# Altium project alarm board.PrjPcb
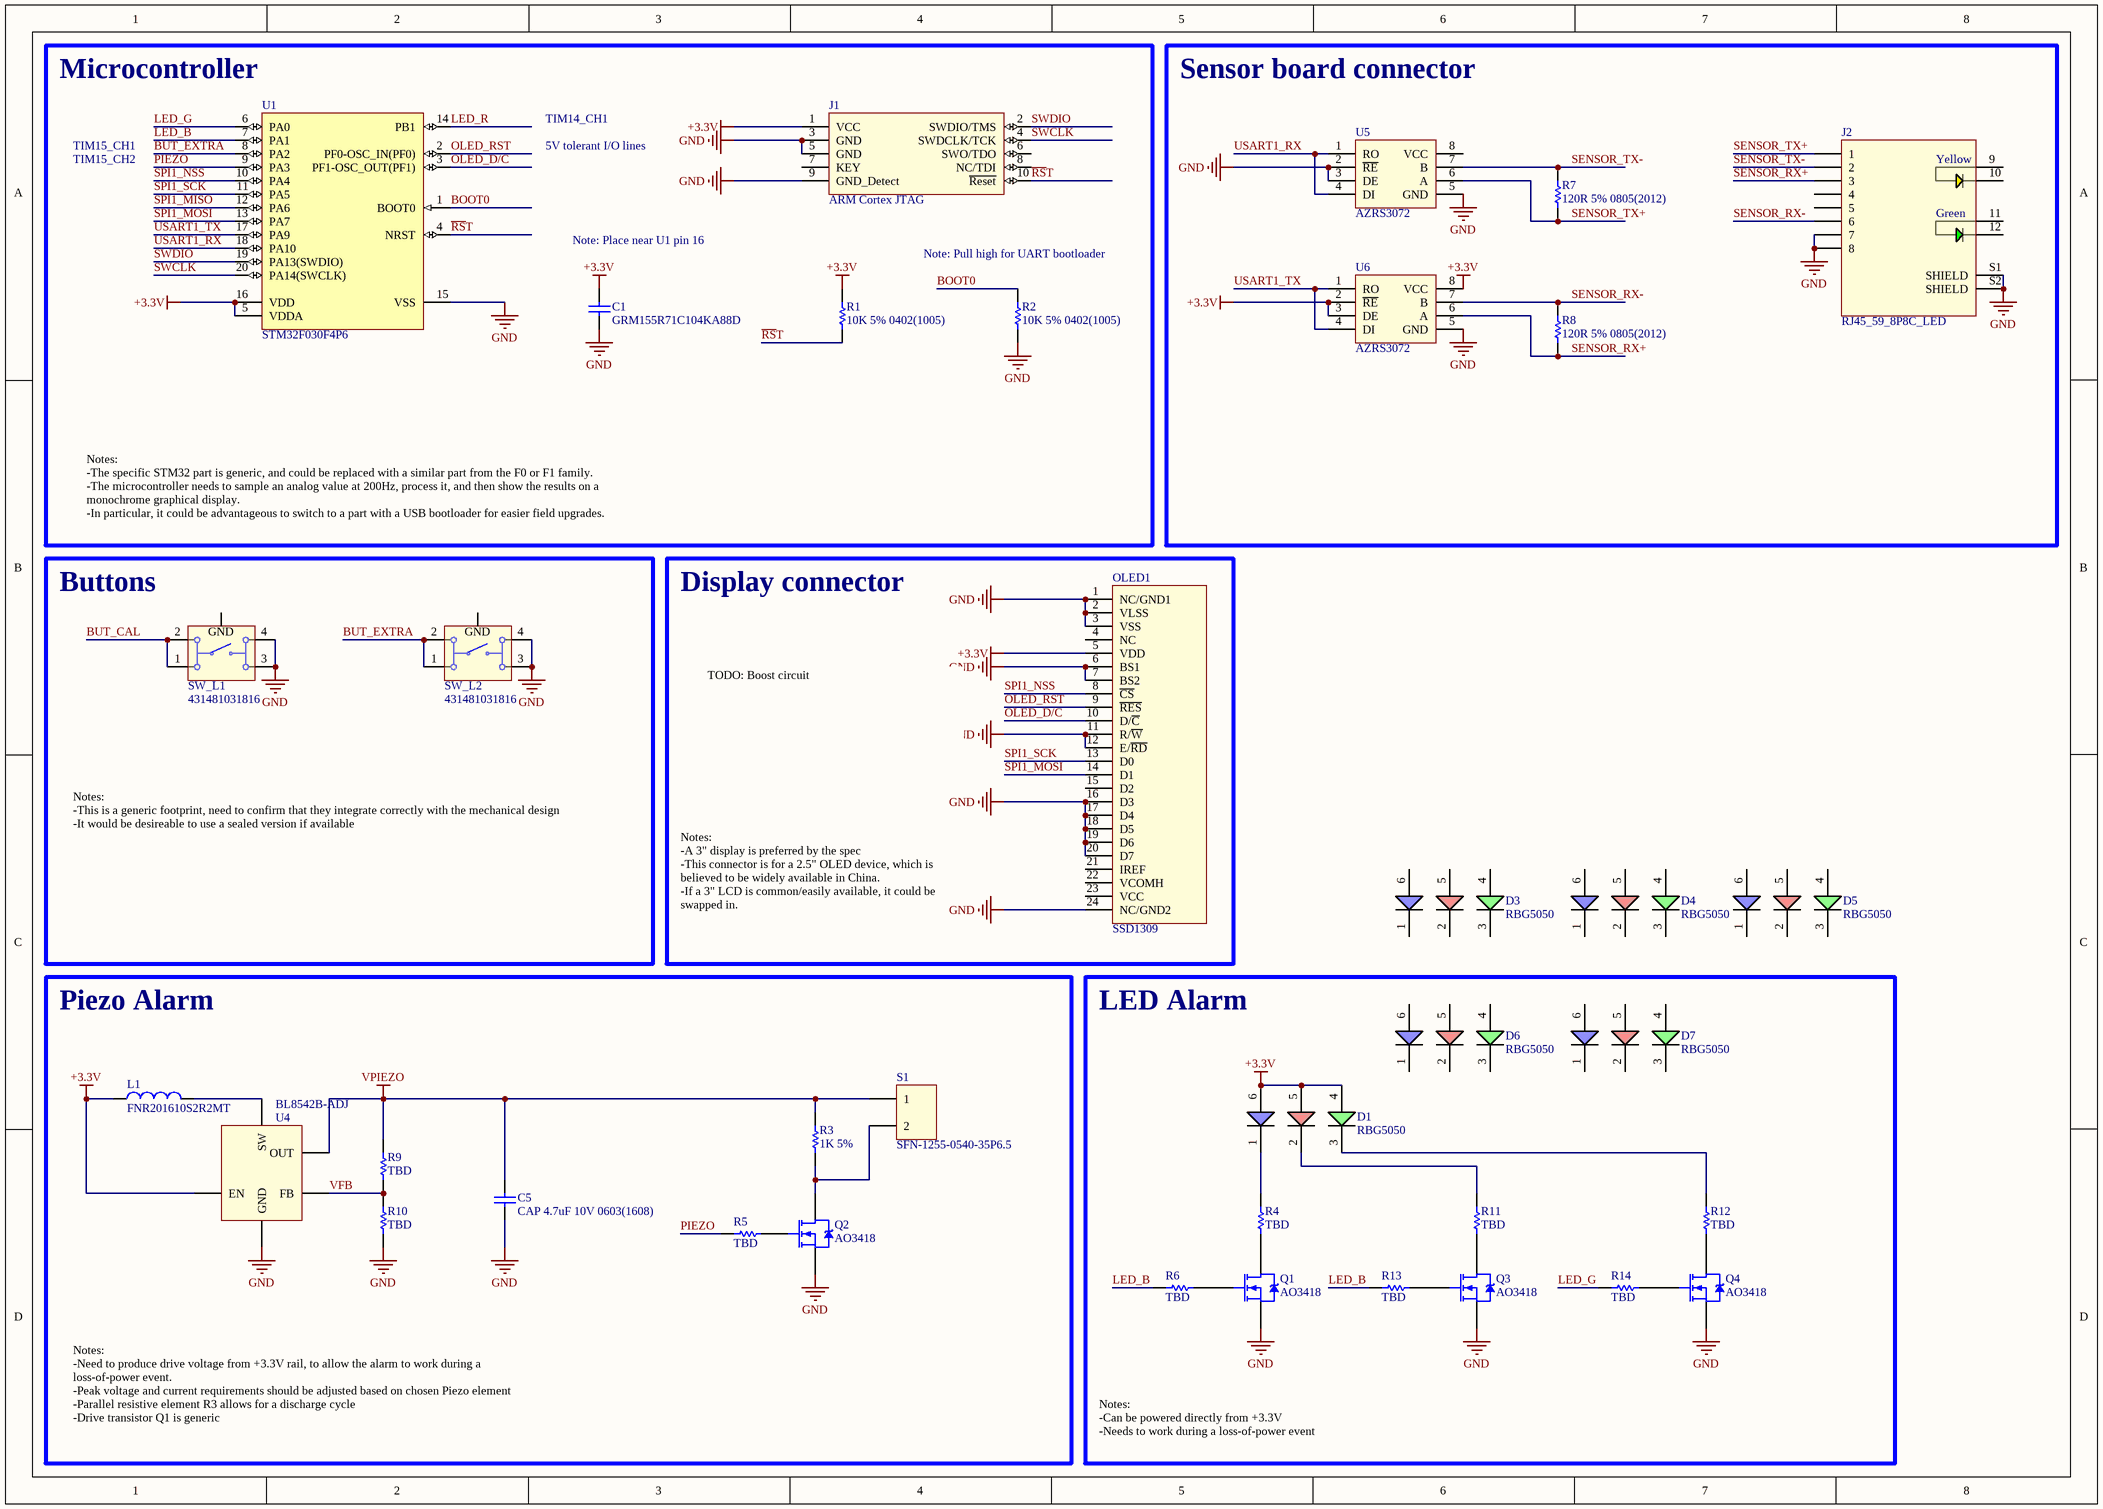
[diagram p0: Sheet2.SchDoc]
2 sheets, 47 parts. Net scope: global (net labels, ports and power ports of the same name join across sheets).
Board file: PCB2.PcbDoc
Sheets:
  Sheet2.SchDoc
  power.SchDoc

## Sheet Sheet2.SchDoc: Alarm Board
size A3

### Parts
C1  GRM155R71C104KA88D  [CAPC1005X55X25ML05T10]
C5  CAP 4.7uF 10V 0603(1608)  [CAPC0603(1608)55_L]
D1  RBG5050  [5050RGB]
D3  RBG5050  [5050RGB]
D4  RBG5050  [5050RGB]
D5  RBG5050  [5050RGB]
D6  RBG5050  [5050RGB]
D7  RBG5050  [5050RGB]
J1  ARM Cortex JTAG  [1.27mm 2x5 SMD Header]
J2  RJ45_59_8P8C_LED  [RJ45_59_8P8C_LED]
L1  FNR201610S2R2MT  [FNR201610S]
OLED1  SSD1309
Q1  AO3418  [SOT95P280X125-3N]
Q2  AO3418  [SOT95P280X125-3N]
Q3  AO3418  [SOT95P280X125-3N]
Q4  AO3418  [SOT95P280X125-3N]
R1  10K 5% 0402(1005)  [RESC0402(1005)_N]
R2  10K 5% 0402(1005)  [RESC0402(1005)_N]
R3  1K 5%  [RESC0402(1005)_N]
R4  TBD  [RESC0402(1005)_N]
R5  TBD  [RESC0402(1005)_N]
R6  TBD  [RESC0402(1005)_N]
R7  120R 5% 0805(2012)  [RESC0805(2012)_N]
R8  120R 5% 0805(2012)  [RESC0805(2012)_N]
R9  TBD  [RESC0402(1005)_N]
R10  TBD  [RESC0402(1005)_N]
R11  TBD  [RESC0402(1005)_N]
R12  TBD  [RESC0402(1005)_N]
R13  TBD  [RESC0402(1005)_N]
R14  TBD  [RESC0402(1005)_N]
S1  SFN-1255-0540-35P6.5  [SFN-1255-0540-35P6.5]
SW_L1  431481031816  [431481031816]
SW_L2  431481031816  [431481031816]
U1  STM32F030F4P6  [STM-TSSOP20_L]
U4  BL8542B-ADJ  [SOT95P280X130-5N]
U5  AZRS3072  [SOIC127P600X175-8N]
U6  AZRS3072  [SOIC127P600X175-8N]

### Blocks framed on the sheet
Microcontroller: C1 J1 R1 R2 U1
Sensor board connector: J2 R7 R8 U5 U6
Buttons: SW_L1 SW_L2
Display connector: OLED1
Piezo Alarm: C5 L1 Q2 R3 R5 R9 R10 S1 U4
LED Alarm: D1 D6 D7 Q1 Q3 Q4 R4 R6 R11-R14

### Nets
+3.3V: C1.2 D1.4 D1.5 D1.6 J1.1(VCC) L1.1 OLED1.5(VDD) R1.1 U1.5(VDDA) U1.16(VDD) U4.3(EN) U6.2(~{RE}) U6.3(DE) U6.8(VCC)
GND: C1.1 C5.1 J1.3(GND) J1.5(GND) J1.9(GND_Detect) J2.7 J2.8 J2.S1(SHIELD) J2.S2(SHIELD) OLED1.1(NC/GND1) OLED1.2(VLSS) OLED1.3(VSS) OLED1.6(BS1) OLED1.7(BS2) OLED1.11(R/~{W}) OLED1.12(E/~{RD}) OLED1.16(D3) OLED1.17(D4) OLED1.18(D5) OLED1.19(D6) OLED1.20(D7) OLED1.24(NC/GND2) Q1.2(SOURCE) Q2.2(SOURCE) Q3.2(SOURCE) Q4.2(SOURCE) R2.2 R10.1 SW_L1.3 SW_L1.4 SW_L2.3 SW_L2.4 U1.15(VSS) U4.2(GND) U5.2(~{RE}) U5.3(DE) U5.5(GND) U6.5(GND)
VPIEZO: C5.2 R3.2 R9.2 S1.1 U4.5(OUT)
~{RS}T: J1.10(~{Reset}) R1.2 U1.4(NRST)
BOOT0: R2.1 U1.1(BOOT0)
BUT_CAL: SW_L1.1 SW_L1.2
BUT_EXTRA: SW_L2.1 SW_L2.2 U1.8(PA2)
LED_B: R6.1 R13.1 U1.7(PA1)
LED_G: R14.1 U1.6(PA0)
LED_R: U1.14(PB1)
OLED_D/C: OLED1.10(D/~{C}) U1.3(PF1-OSC_OUT(PF1))
OLED_RST: OLED1.9(~{RES}) U1.2(PF0-OSC_IN(PF0))
PIEZO: R5.1 U1.9(PA3)
SENSOR_RX+: J2.3 R8.1 U6.6(A)
SENSOR_RX-: J2.6 R8.2 U6.7(B)
SENSOR_TX+: J2.1 R7.1 U5.6(A)
SENSOR_TX-: J2.2 R7.2 U5.7(B)
SPI1_MISO: U1.12(PA6)
SPI1_MOSI: OLED1.14(D1) U1.13(PA7)
SPI1_NSS: OLED1.8(~{CS}) U1.10(PA4)
SPI1_SCK: OLED1.13(D0) U1.11(PA5)
SWCLK: J1.4(SWDCLK/TCK) U1.20(PA14(SWCLK))
SWDIO: J1.2(SWDIO/TMS) U1.19(PA13(SWDIO))
USART1_RX: U1.18(PA10) U5.1(RO) U5.4(DI)
USART1_TX: U1.17(PA9) U6.1(RO) U6.4(DI)
VFB: R9.1 R10.2 U4.1(FB)
NetD1_1: D1.1 R4.2
NetD1_2: D1.2 R11.2
NetD1_3: D1.3 R12.2
NetL1_2: L1.2 U4.4(SW)
NetQ1_1: Q1.1(GATE) R6.2
NetQ1_3: Q1.3(DRAIN) R4.1
NetQ2_3: Q2.3(DRAIN) R3.1 S1.2
NetQ3_1: Q3.1(GATE) R13.2
NetQ3_3: Q3.3(DRAIN) R11.1
NetQ4_1: Q4.1(GATE) R14.2
NetQ4_3: Q4.3(DRAIN) R12.1

Not connected (* = marked no-connect by the designer): D3 1 2 3 4 5 6; D4 1 2 3 4 5 6; D5 1 2 3 4 5 6; D6 1 2 3 4 5 6; D7 1 2 3 4 5 6; J1 6(SWO/TDO) 7(KEY) 8(NC/TDI); J2 4 5 9(Yellow_Anode) 10(Yellow_Cathode) 11(Green_Anode) 12(Green_Cathode); OLED1 4(NC) 15(D2) 21(IREF) 22(VCOMH) 23(VCC); Q2 1(GATE); R5 2; SW_L1 5; SW_L2 5; U5 8(VCC)

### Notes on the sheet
- TIM15_CH2
- TIM15_CH1
- TIM14_CH1
- 5V tolerant I/O lines
- Note: Place near U1 pin 16
- (near R2) Note: Pull high for UART bootloader
- Notes:
  -The specific STM32 part is generic, and could be replaced with a similar part from the F0 or F1 family.
  -The microcontroller needs to sample an analog value at 200Hz, process it, and then show the results on a monochrome graphical display.
  -In particular, it could be advantageous to switch to a part with a USB bootloader for easier field upgrades.
- TODO: Boost circuit
- Notes:
  -This is a generic footprint, need to confirm that they integrate correctly with the mechanical design
  -It would be desireable to use a sealed version if available
- Notes:
  -A 3" display is preferred by the spec
  -This connector is for a 2.5" OLED device, which is believed to be widely available in China.
  -If a 3" LCD is common/easily available, it could be swapped in.
- Notes:
  -Need to produce drive voltage from +3.3V rail, to allow the alarm to work during a loss-of-power event.
  -Peak voltage and current requirements should be adjusted based on chosen Piezo element
  -Parallel resistive element R3 allows for a discharge cycle
  -Drive transistor Q1 is generic
- Notes:
  -Can be powered directly from +3.3V
  -Needs to work during a loss-of-power event

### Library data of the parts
C1 = CMP-2100-03641-1: Chip Capacitor, 0.1 uF, +/- 10%, 16 V, -55 to 125 degC, 0402 (1005 Metric), RoHS, Tape and Reel; Manufacturer: Murata; Material: Ceramic; Insulation Resistance: 10GR; Voltage: 16V; Dielectric: X7R; Capacitance: 100nF
C5 = CMP-1035-02784-1: CAP 4.7uF 10V ±10% 0603 (1608 Metric) Thickness 0.55mm SMD; Case-Metric: 1608; Tolerance: Â±10%; Case-EIA: 0603
D1 D3-D7 = RBG5050: Generic RGB LED in 5050 package. Note that several variants exist, so check the pinout!; PartNumber: Unknown/Generic
J1 = ARM Cortex JTAG: Arm Cortex 10-pin JTAG connector; Manufacturer: Unknown/Generic
J2 = RJ45_59_8P8C_LED: Generic RJ49 jack with LED and without magnetics; Manufacturer: Unknown/Generic
L1 = FNR201610S2R2MT: Wire Wound SMD Power Inductors 2.0×1.6×1.0 2.2uH
OLED1 = SSD1309: 2.4" OLED display, 24-pin connector, SSD1309 driver IC
Q1-Q4 = AO3418: 30V N-Channel MOSFET; Manufacturer: Alpha & Omega
R1-R6 R9-R14 = CMP-1011-00098-1: 10K 0.063W 5% 0402 (1005 Metric)  SMD; Case-Metric: 1005; Value: 10000.00 Ohm; Case-EIA: 0402
R7 R8 = CMP-1013-00052-1: 120R 0.125W 5% 0805 (2012 Metric)  SMD; Case-Metric: 2012; Value: 120.00 Ohm; Case-EIA: 0805
S1 = SFN-1255-0540-35P6.5: Piezo Buzzer, 4KHz; Manufacturer: S&S
SW_L1 SW_L2 = CMP-1457-00011-1: WS-TASV SMD Tact Switch 6X6 mm with ground terminal; Manufacturer: Wuerth Elektronik; NoPins: 04
U1 = CMP-0304-00039-2: ARM Cortex-M0 32-bit MCU, 16 KB Flash, 4 KB Internal RAM, 15 I/Os, 20-pin TSSOP, -40 to 85 degC, Tube; I/Os (High Current): 15; FLASH Size (Prog) (kB): 16; Internal RAM Size (kB): 4; Supply Voltage(Vcc) min (V): 2.4; Operating Frequency(F) (Processor speed) (MHz): 48
U4 = BL8542B-ADJ: 0.85V startup, 1MHz, 300mA Iout,  Synchronous Boost Converter (adjustable output)
U5 U6 = AZRS3072: ESD-Protected, Slew-Rate-Limited, True Fail-Safe 3.3V RS485 Transceiver IC; Manufacturer: Amazing Microelectronic Corp.

## Sheet power.SchDoc: Power Supply
size A4
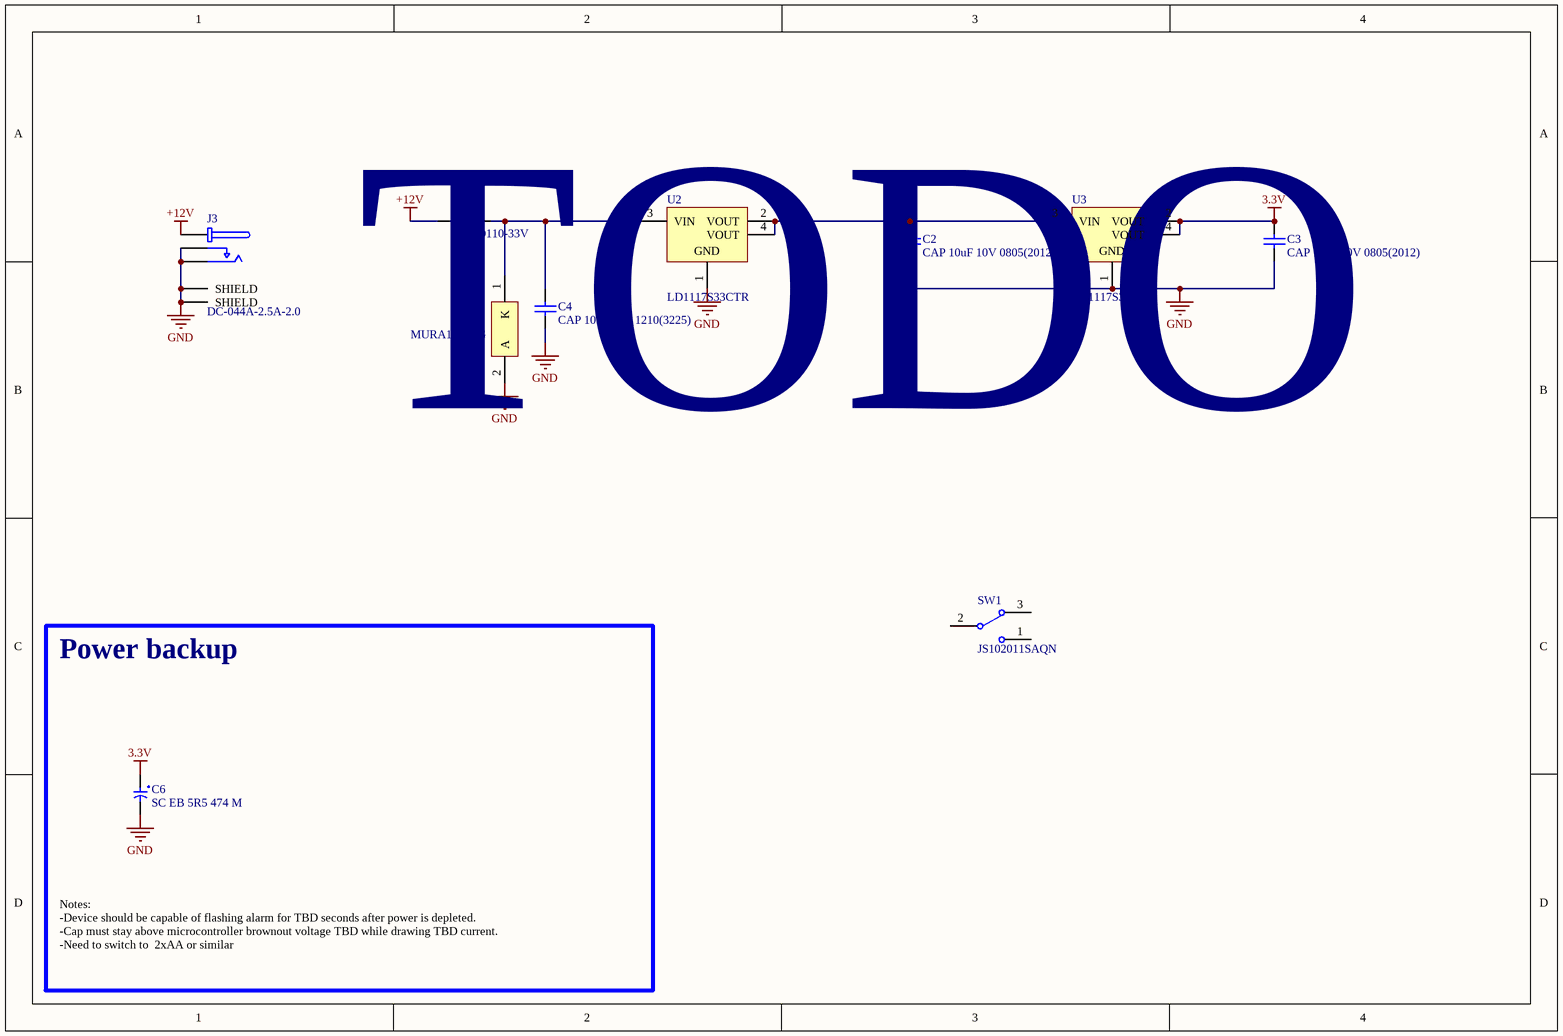
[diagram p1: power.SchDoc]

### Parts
C2  CAP 10uF 10V 0805(2012)  [CAPC0805(2012)145_N]
C3  CAP 10uF 10V 0805(2012)  [CAPC0805(2012)145_N]
C4  CAP 10uF 50V 1210(3225)  [CAPC1210(3225)190_N]
C6  SC EB 5R5 474 M  [SC EB 5R5 474 M]
D2  MURA110T3G  [ONSC-SMA-2-403D-02_V]
F1  mSMD110-33V  [SEAANDLAND_1812]
J3  DC-044A-2.5A-2.0  [DC-044A-2.5A-2.0]
SW1  JS102011SAQN  [CKCP-JS102011SAQN-3_V]
U2  LD1117S33CTR  [SOT-223_N]
U3  LD1117S33CTR  [SOT-223_N]

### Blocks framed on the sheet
Power backup: C6

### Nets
3.3V: C3.2 C6.1 U3.2(VOUT) U3.4(VOUT)
9V: C2.2 U2.2(VOUT) U2.4(VOUT) U3.3(VIN)
+12V: F1.1 J3.1
GND: C2.1 C3.1 C4.1 C6.2 D2.2(A) J3.2 J3.3 J3.4(SHIELD) J3.5(SHIELD) U2.1(GND) U3.1(GND)
NetC4_2: C4.2 D2.1(K) F1.2 U2.3(VIN)

Not connected (* = marked no-connect by the designer): SW1 1 2 3

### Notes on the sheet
- TODO
- Notes:
  -Device should be capable of flashing alarm for TBD seconds after power is depleted.
  -Cap must stay above microcontroller brownout voltage TBD while drawing TBD current.
  -Need to switch to  2xAA or similar

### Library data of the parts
C2 C3 = CMP-1036-04922-1: CAP 10uF 10V ±10% 0805 (2012 Metric) Thickness 1.45mm SMD; Tolerance: Â±10%; Case-EIA: 0805; Case-Metric: 2012
C4 = CMP-1038-02238-1: CAP 10uF 50V -20% to +80% 1210 (3225 Metric) Thickness 1.9mm SMD; Case-Metric: 3225; Case-EIA: 1210
C6 = SC EB 5R5 474 M: Wincap .47F, 5.5V, thru-hole supercap
D2 = CMP-0902-00293-1: Surface Mount Ultrafast Power Rectifier, 2-Pin SMA, Pb-Free, Tape and Reel; Manufacturer: On Semiconductor; IFSM Max (A): 50
F1 = mSMD110-33V: Surface Mount Fuses 33V 100A 1.1A 2.2A 1812 RoHS; Manufacturer: Sea & Land Electronic Corp
J3 = DC-044A-2.5A-2.0: DC Jack, 6mm OD, 2mm ID; Manufacturer: XKB
SW1 = CMP-2000-06501-1: Sub-Miniature Slide Switch, SPDT, -40 to 85 degC, 3-Pin SMD, RoHS, Tape and Reel; Manufacturer: C&K Components; Electrical Life: 15000Cycles; Actuator Color: Black; Body Orientation: RightAngle; Minimum Insulation Resistance: 100MOhm; Contact Rating @ Voltage: 0.3@6VDCA; Actuator Style: SideSlide; Maximum DC Voltage Rating: 6V; COO: US; Actuator Material: Nylon4/6; Dielectric Strength: 500VAC; Maximum Contact Resistance: 70mOhm
U2 U3 = CMP-0244-00307-1: Fixed Low Drop Positive Voltage Regulator, 3.3V, 4-Pin SOT-223, Tape and Reel

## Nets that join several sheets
GND: Sheet2 (38 pins), power (11 pins)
